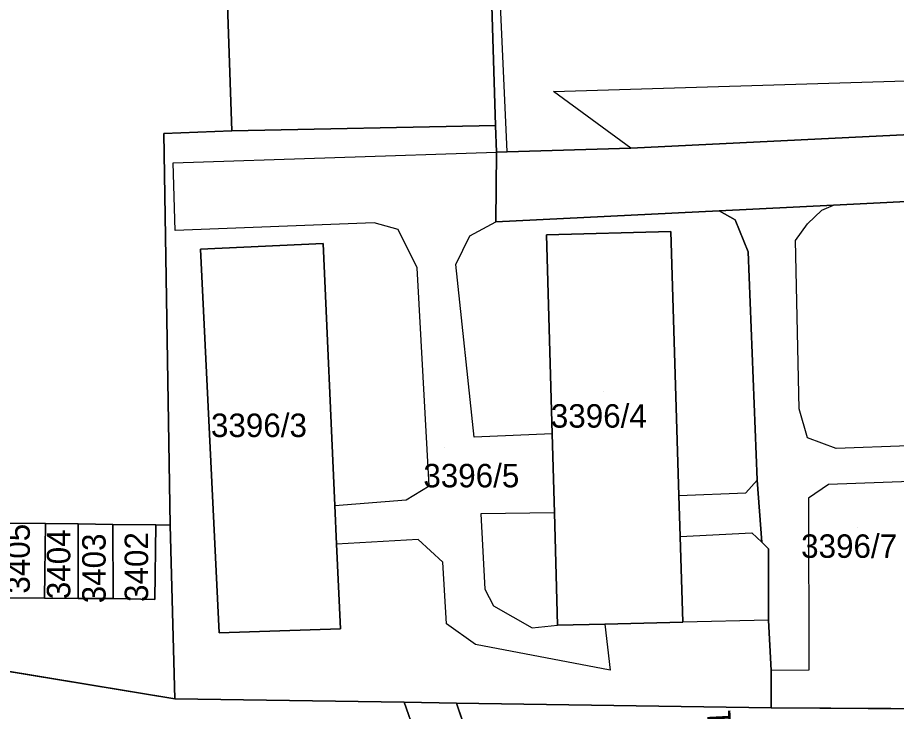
# Model space of a CAD drawing. Extents: x -264070 to -262271, y -1238894 to -1238141.
# Drawn here: x -262723.1 to -262648.2, y -1238480.7 to -1238421.6 of the extents above; entities that cross this region are included whole.
import ezdxf

# ---------------------------------------------------------------- set-up
doc = ezdxf.new("R2010")
doc.units = 0
for name, color, linetype in [('body_kn', 7, 'Continuous'), ('kladpar_druhypozemkov', 7, 'Continuous'), ('kladpar_hranice', 7, 'Continuous'), ('kladpar_parcelnecisla', 7, 'Continuous'), ('kladpar_plochy', 7, 'Continuous'), ('zappar_hrandruhpozemk', 7, 'Continuous')]:
    doc.layers.add(name, color=color, linetype=linetype)

msp = doc.modelspace()

# ---------------------------------------------------------------- linework, layer by layer
at = {"layer": 'body_kn'}
for p, q in [((-262677.41, -1238427.88), (-262677.41, -1238427.88)), ((-262682.33, -1238430.79), (-262682.33, -1238430.79)), ((-262682.33, -1238430.79), (-262682.33, -1238430.79)), ((-262710.6, -1238431.46), (-262710.6, -1238431.46)), ((-262704.82, -1238431.24), (-262704.82, -1238431.24)), ((-262682.26, -1238433.07), (-262682.26, -1238433.07)), ((-262681.34, -1238433.03), (-262681.34, -1238433.03)), ((-262681.34, -1238433.03), (-262681.34, -1238433.03)), ((-262670.81, -1238432.73), (-262670.81, -1238432.73)), ((-262670.81, -1238432.73), (-262670.81, -1238432.73)), ((-262709.82, -1238433.98), (-262709.82, -1238433.98)), ((-262653.53, -1238437.57), (-262653.53, -1238437.57)), ((-262653.53, -1238437.57), (-262653.53, -1238437.57)), ((-262663.29, -1238438.06), (-262663.29, -1238438.06)), ((-262654.54, -1238438.01), (-262654.54, -1238438.01)), ((-262692.67, -1238439.1), (-262692.67, -1238439.1)), ((-262682.32, -1238439.01), (-262682.32, -1238439.01)), ((-262661.93, -1238438.83), (-262661.93, -1238438.83)), ((-262709.63, -1238439.73), (-262709.63, -1238439.73)), ((-262690.62, -1238439.65), (-262690.62, -1238439.65)), ((-262667.41, -1238439.84), (-262667.41, -1238439.84)), ((-262667.41, -1238439.84), (-262667.41, -1238439.84)), ((-262655.76, -1238439.16), (-262655.76, -1238439.16)), ((-262684.53, -1238440.19), (-262684.53, -1238440.19)), ((-262678, -1238440.1), (-262678, -1238440.1)), ((-262656.79, -1238440.59), (-262656.79, -1238440.59)), ((-262707.47, -1238441.34), (-262707.47, -1238441.34)), ((-262697.02, -1238440.86), (-262697.02, -1238440.86)), ((-262697.02, -1238440.86), (-262697.02, -1238440.86)), ((-262660.8, -1238441.56), (-262660.8, -1238441.56)), ((-262685.72, -1238442.65), (-262685.72, -1238442.65)), ((-262689.02, -1238442.92), (-262689.02, -1238442.92)), ((-262656.46, -1238454.95), (-262656.46, -1238454.95)), ((-262684.17, -1238457.37), (-262684.17, -1238457.37)), ((-262677.51, -1238457.08), (-262677.51, -1238457.08)), ((-262677.51, -1238457.08), (-262677.51, -1238457.08)), ((-262655.76, -1238457.42), (-262655.76, -1238457.42)), ((-262653.31, -1238458.32), (-262653.31, -1238458.32)), ((-262687.98, -1238461.52), (-262687.98, -1238461.52)), ((-262660.03, -1238461.01), (-262660.03, -1238461.01)), ((-262660.03, -1238461.03), (-262660.03, -1238461.03)), ((-262653.97, -1238461.41), (-262653.97, -1238461.41)), ((-262661, -1238462.1), (-262661, -1238462.1)), ((-262689.96, -1238462.71), (-262689.96, -1238462.71)), ((-262666.71, -1238462.33), (-262666.71, -1238462.33)), ((-262666.71, -1238462.33), (-262666.71, -1238462.33)), ((-262655.66, -1238462.56), (-262655.66, -1238462.56)), ((-262696.02, -1238463.2), (-262696.02, -1238463.2)), ((-262696.02, -1238463.2), (-262696.02, -1238463.2)), ((-262677.32, -1238463.8), (-262677.32, -1238463.8)), ((-262677.32, -1238463.8), (-262677.32, -1238463.8)), ((-262683.59, -1238463.89), (-262683.59, -1238463.89)), ((-262720.69, -1238464.72), (-262720.69, -1238464.72)), ((-262720.69, -1238464.72), (-262720.69, -1238464.72)), ((-262717.89, -1238464.76), (-262717.89, -1238464.76)), ((-262717.89, -1238464.76), (-262717.89, -1238464.76)), ((-262714.94, -1238464.8), (-262714.94, -1238464.8)), ((-262714.94, -1238464.8), (-262714.94, -1238464.8)), ((-262711.29, -1238464.84), (-262711.29, -1238464.84)), ((-262711.29, -1238464.84), (-262711.29, -1238464.84)), ((-262710.05, -1238464.86), (-262710.05, -1238464.86)), ((-262666.6, -1238465.83), (-262666.6, -1238465.83)), ((-262666.6, -1238465.83), (-262666.6, -1238465.83)), ((-262660.5, -1238465.52), (-262660.5, -1238465.52)), ((-262695.88, -1238466.48), (-262695.88, -1238466.48)), ((-262688.93, -1238466.08), (-262688.93, -1238466.08)), ((-262659.65, -1238466.31), (-262659.65, -1238466.31)), ((-262659.08, -1238466.87), (-262659.08, -1238466.87)), ((-262686.84, -1238468.01), (-262686.84, -1238468.01)), ((-262683.25, -1238470.32), (-262683.25, -1238470.32)), ((-262720.77, -1238471.08), (-262720.77, -1238471.08)), ((-262717.91, -1238471.13), (-262717.91, -1238471.13)), ((-262714.92, -1238471.13), (-262714.92, -1238471.13)), ((-262711.37, -1238471.21), (-262711.37, -1238471.21)), ((-262682.51, -1238471.75), (-262682.51, -1238471.75)), ((-262686.51, -1238473.27), (-262686.51, -1238473.27)), ((-262677.05, -1238473.4), (-262677.05, -1238473.4)), ((-262673.01, -1238473.3), (-262673.01, -1238473.3)), ((-262673.01, -1238473.3), (-262673.01, -1238473.3)), ((-262666.38, -1238473.14), (-262666.38, -1238473.14)), ((-262659.07, -1238472.97), (-262659.07, -1238472.97)), ((-262659.07, -1238472.97), (-262659.07, -1238472.97)), ((-262705.88, -1238474.04), (-262705.88, -1238474.04)), ((-262695.56, -1238473.7), (-262695.56, -1238473.7)), ((-262679.22, -1238473.63), (-262679.22, -1238473.63)), ((-262684.03, -1238475.03), (-262684.03, -1238475.03)), ((-262672.58, -1238477.23), (-262672.58, -1238477.23)), ((-262658.86, -1238477.25), (-262658.86, -1238477.25)), ((-262655.63, -1238477.22), (-262655.63, -1238477.22)), ((-262709.67, -1238479.66), (-262709.67, -1238479.66)), ((-262690.11, -1238479.96), (-262690.11, -1238479.96)), ((-262690.11, -1238479.96), (-262690.11, -1238479.96)), ((-262685.67, -1238480.03), (-262685.67, -1238480.03)), ((-262658.86, -1238480.45), (-262658.86, -1238480.45))]:
    msp.add_line(p, q, dxfattribs=at)
at = {"layer": 'kladpar_druhypozemkov'}
for p, q in [((-262673.13, -1238453.45), (-262673.13, -1238453.45)), ((-262701.43, -1238455.05), (-262701.43, -1238455.05)), ((-262686.68, -1238458.26), (-262686.68, -1238458.26)), ((-262651.5, -1238465.1), (-262651.5, -1238465.1)), ((-262719.97, -1238468.13), (-262719.97, -1238468.13)), ((-262717.07, -1238468.28), (-262717.07, -1238468.28)), ((-262713.8, -1238468.49), (-262713.8, -1238468.49))]:
    msp.add_line(p, q, dxfattribs=at)
at = {"layer": 'kladpar_hranice'}
for p, q in [((-262704.82, -1238431.24), (-262682.33, -1238430.79)), ((-262663.29, -1238438.06), (-262653.53, -1238437.57)), ((-262709.67, -1238479.66), (-262690.11, -1238479.96))]:
    msp.add_line(p, q, dxfattribs=at)
for points in [[(-262727.62, -1238375.13), (-262720.72, -1238374.82), (-262719.4, -1238374.76), (-262719.22, -1238391.06), (-262706.19, -1238390.68), (-262704.82, -1238431.24), (-262710.6, -1238431.46), (-262710.05, -1238464.86), (-262711.29, -1238464.84), (-262714.94, -1238464.8), (-262717.89, -1238464.76), (-262720.69, -1238464.72), (-262723.82, -1238464.68)], [(-262642.76, -1238409.16), (-262642.44, -1238426.82), (-262642.39, -1238429.37), (-262623.26, -1238428.79), (-262623.19, -1238430.38), (-262670.81, -1238432.73), (-262681.34, -1238433.03), (-262682.26, -1238433.07), (-262682.33, -1238430.79), (-262683.59, -1238389.92), (-262657.38, -1238389.22), (-262651.01, -1238389.03), (-262650.49, -1238390.42), (-262643.12, -1238390.23), (-262643.09, -1238393.83), (-262682.26, -1238395.14), (-262681.73, -1238410.21), (-262642.76, -1238409.16)], [(-262683.59, -1238389.92), (-262682.33, -1238430.79), (-262704.82, -1238431.24), (-262706.19, -1238390.68), (-262683.59, -1238389.92)], [(-262528.81, -1238443.27), (-262550.25, -1238441.7), (-262558.38, -1238440.81), (-262565.14, -1238438.89), (-262571.97, -1238436.07), (-262583.91, -1238434.36), (-262593.16, -1238434.55), (-262602.72, -1238435.03), (-262622.62, -1238436.02), (-262634.86, -1238436.64), (-262653.53, -1238437.57), (-262663.29, -1238438.06), (-262682.32, -1238439.01), (-262682.26, -1238433.07), (-262681.34, -1238433.03), (-262670.81, -1238432.73), (-262623.19, -1238430.38), (-262610.89, -1238429.75), (-262587.08, -1238428.65)], [(-262682.33, -1238430.79), (-262682.26, -1238433.07), (-262682.32, -1238439.01), (-262663.29, -1238438.06), (-262661.93, -1238438.83), (-262660.8, -1238441.56), (-262660.03, -1238461.01), (-262660.03, -1238461.03), (-262659.65, -1238466.31), (-262659.08, -1238466.87), (-262659.07, -1238472.97), (-262658.86, -1238477.25), (-262658.86, -1238480.45), (-262685.67, -1238480.03), (-262690.11, -1238479.96), (-262709.67, -1238479.66), (-262710.05, -1238464.86), (-262710.6, -1238431.46), (-262704.82, -1238431.24)], [(-262653.53, -1238437.57), (-262634.86, -1238436.64), (-262632.24, -1238437.35), (-262631.44, -1238437.94), (-262630.97, -1238438.64), (-262630.56, -1238439.54), (-262630.46, -1238440.24), (-262628.6, -1238477.34), (-262628.35, -1238477.3), (-262628.25, -1238480.62), (-262658.86, -1238480.45), (-262658.86, -1238477.25), (-262659.07, -1238472.97), (-262659.08, -1238466.87), (-262659.65, -1238466.31), (-262660.03, -1238461.03), (-262660.03, -1238461.01), (-262660.8, -1238441.56), (-262661.93, -1238438.83), (-262663.29, -1238438.06)], [(-262678, -1238440.1), (-262677.51, -1238457.08), (-262677.32, -1238463.8), (-262677.05, -1238473.4), (-262673.01, -1238473.3), (-262666.38, -1238473.14), (-262666.6, -1238465.83), (-262666.71, -1238462.33), (-262667.41, -1238439.84), (-262678, -1238440.1)], [(-262667.41, -1238439.84), (-262666.71, -1238462.33), (-262666.6, -1238465.83), (-262666.38, -1238473.14), (-262673.01, -1238473.3), (-262677.05, -1238473.4), (-262677.32, -1238463.8), (-262677.51, -1238457.08), (-262678, -1238440.1), (-262667.41, -1238439.84)], [(-262695.56, -1238473.7), (-262695.88, -1238466.48), (-262696.02, -1238463.2), (-262697.02, -1238440.86), (-262707.47, -1238441.34), (-262705.88, -1238474.04), (-262695.56, -1238473.7)], [(-262697.02, -1238440.86), (-262696.02, -1238463.2), (-262695.88, -1238466.48), (-262695.56, -1238473.7), (-262705.88, -1238474.04), (-262707.47, -1238441.34), (-262697.02, -1238440.86)], [(-262723.91, -1238471.05), (-262720.77, -1238471.08), (-262717.91, -1238471.13), (-262714.92, -1238471.13), (-262711.37, -1238471.21), (-262711.29, -1238464.84), (-262710.05, -1238464.86), (-262709.67, -1238479.66), (-262729.53, -1238476.4)], [(-262720.69, -1238464.72), (-262720.77, -1238471.08), (-262723.91, -1238471.05), (-262723.82, -1238464.68), (-262720.69, -1238464.72)], [(-262717.89, -1238464.76), (-262717.91, -1238471.13), (-262720.77, -1238471.08), (-262720.69, -1238464.72), (-262717.89, -1238464.76)], [(-262714.94, -1238464.8), (-262714.92, -1238471.13), (-262717.91, -1238471.13), (-262717.89, -1238464.76), (-262714.94, -1238464.8)], [(-262711.29, -1238464.84), (-262711.37, -1238471.21), (-262714.92, -1238471.13), (-262714.94, -1238464.8), (-262711.29, -1238464.84)], [(-262677.42, -1238504.32), (-262685.67, -1238480.03), (-262658.86, -1238480.45), (-262628.25, -1238480.62), (-262619.15, -1238480.68), (-262602.39, -1238476.75), (-262595.04, -1238471.11)], [(-262729.53, -1238476.4), (-262709.67, -1238479.66)], [(-262677.42, -1238504.32), (-262675.32, -1238509.87), (-262674.44, -1238511.49), (-262673.46, -1238512.89), (-262678.41, -1238514.42), (-262680.86, -1238507.1), (-262681.36, -1238505.58), (-262685.87, -1238492.37), (-262686.4, -1238490.8), (-262687.99, -1238486.14), (-262689.19, -1238482.63), (-262690.11, -1238479.96), (-262685.67, -1238480.03), (-262677.42, -1238504.32)], [(-262690.11, -1238479.96), (-262689.19, -1238482.63)]]:
    msp.add_lwpolyline(points, dxfattribs=at)
at = {"layer": 'kladpar_plochy'}
for p, q in [((-262704.82, -1238431.24), (-262682.33, -1238430.79)), ((-262682.33, -1238430.79), (-262682.26, -1238433.07)), ((-262710.6, -1238431.46), (-262704.82, -1238431.24)), ((-262710.05, -1238464.86), (-262710.6, -1238431.46)), ((-262682.26, -1238433.07), (-262682.32, -1238439.01)), ((-262653.53, -1238437.57), (-262634.86, -1238436.64)), ((-262663.29, -1238438.06), (-262653.53, -1238437.57)), ((-262682.32, -1238439.01), (-262663.29, -1238438.06)), ((-262661.93, -1238438.83), (-262663.29, -1238438.06)), ((-262663.29, -1238438.06), (-262661.93, -1238438.83)), ((-262660.8, -1238441.56), (-262661.93, -1238438.83)), ((-262661.93, -1238438.83), (-262660.8, -1238441.56)), ((-262667.41, -1238439.84), (-262678, -1238440.1)), ((-262666.71, -1238462.33), (-262667.41, -1238439.84)), ((-262678, -1238440.1), (-262677.51, -1238457.08)), ((-262697.02, -1238440.86), (-262707.47, -1238441.34)), ((-262707.47, -1238441.34), (-262705.88, -1238474.04)), ((-262696.02, -1238463.2), (-262697.02, -1238440.86)), ((-262660.03, -1238461.01), (-262660.8, -1238441.56)), ((-262660.8, -1238441.56), (-262660.03, -1238461.01)), ((-262677.51, -1238457.08), (-262677.32, -1238463.8)), ((-262660.03, -1238461.03), (-262660.03, -1238461.01)), ((-262660.03, -1238461.01), (-262660.03, -1238461.03)), ((-262659.65, -1238466.31), (-262660.03, -1238461.03)), ((-262660.03, -1238461.03), (-262659.65, -1238466.31)), ((-262666.6, -1238465.83), (-262666.71, -1238462.33)), ((-262695.88, -1238466.48), (-262696.02, -1238463.2)), ((-262677.32, -1238463.8), (-262677.05, -1238473.4)), ((-262711.37, -1238471.21), (-262711.29, -1238464.84)), ((-262711.29, -1238464.84), (-262710.05, -1238464.86)), ((-262710.05, -1238464.86), (-262709.67, -1238479.66)), ((-262709.67, -1238479.66), (-262710.05, -1238464.86)), ((-262666.38, -1238473.14), (-262666.6, -1238465.83)), ((-262695.56, -1238473.7), (-262695.88, -1238466.48)), ((-262659.08, -1238466.87), (-262659.65, -1238466.31)), ((-262659.65, -1238466.31), (-262659.08, -1238466.87)), ((-262659.07, -1238472.97), (-262659.08, -1238466.87)), ((-262659.08, -1238466.87), (-262659.07, -1238472.97)), ((-262723.91, -1238471.05), (-262720.77, -1238471.08)), ((-262720.77, -1238471.08), (-262717.91, -1238471.13)), ((-262717.91, -1238471.13), (-262714.92, -1238471.13)), ((-262714.92, -1238471.13), (-262711.37, -1238471.21)), ((-262677.05, -1238473.4), (-262673.01, -1238473.3)), ((-262673.01, -1238473.3), (-262666.38, -1238473.14)), ((-262658.86, -1238477.25), (-262659.07, -1238472.97)), ((-262659.07, -1238472.97), (-262658.86, -1238477.25)), ((-262705.88, -1238474.04), (-262695.56, -1238473.7)), ((-262709.67, -1238479.66), (-262729.53, -1238476.4)), ((-262729.53, -1238476.4), (-262709.67, -1238479.66)), ((-262658.86, -1238480.45), (-262658.86, -1238477.25)), ((-262658.86, -1238477.25), (-262658.86, -1238480.45)), ((-262690.11, -1238479.96), (-262709.67, -1238479.66)), ((-262709.67, -1238479.66), (-262690.11, -1238479.96)), ((-262685.67, -1238480.03), (-262690.11, -1238479.96)), ((-262690.11, -1238479.96), (-262689.19, -1238482.63)), ((-262658.86, -1238480.45), (-262685.67, -1238480.03)), ((-262677.42, -1238504.32), (-262685.67, -1238480.03)), ((-262685.67, -1238480.03), (-262658.86, -1238480.45)), ((-262628.25, -1238480.62), (-262658.86, -1238480.45)), ((-262658.86, -1238480.45), (-262628.25, -1238480.62))]:
    msp.add_line(p, q, dxfattribs=at)
for points in [[(-262727.62, -1238375.13), (-262720.72, -1238374.82), (-262719.4, -1238374.76), (-262719.22, -1238391.06), (-262706.19, -1238390.68), (-262704.82, -1238431.24), (-262710.6, -1238431.46), (-262710.05, -1238464.86), (-262711.29, -1238464.84), (-262714.94, -1238464.8), (-262717.89, -1238464.76), (-262720.69, -1238464.72), (-262723.82, -1238464.68)], [(-262634.86, -1238436.64), (-262653.53, -1238437.57), (-262663.29, -1238438.06), (-262682.32, -1238439.01), (-262682.26, -1238433.07), (-262681.34, -1238433.03), (-262670.81, -1238432.73), (-262623.19, -1238430.38)]]:
    msp.add_lwpolyline(points, dxfattribs=at)
for points in [[(-262642.76, -1238409.16), (-262642.44, -1238426.82), (-262642.39, -1238429.37), (-262623.26, -1238428.79), (-262623.19, -1238430.38), (-262670.81, -1238432.73), (-262681.34, -1238433.03), (-262682.26, -1238433.07), (-262682.33, -1238430.79), (-262683.59, -1238389.92), (-262657.38, -1238389.22), (-262651.01, -1238389.03), (-262650.49, -1238390.42), (-262643.12, -1238390.23), (-262643.09, -1238393.83), (-262682.26, -1238395.14), (-262681.73, -1238410.21)], [(-262683.59, -1238389.92), (-262682.33, -1238430.79), (-262704.82, -1238431.24), (-262706.19, -1238390.68)], [(-262667.41, -1238439.84), (-262666.71, -1238462.33), (-262666.6, -1238465.83), (-262666.38, -1238473.14), (-262673.01, -1238473.3), (-262677.05, -1238473.4), (-262677.32, -1238463.8), (-262677.51, -1238457.08), (-262678, -1238440.1)], [(-262697.02, -1238440.86), (-262696.02, -1238463.2), (-262695.88, -1238466.48), (-262695.56, -1238473.7), (-262705.88, -1238474.04), (-262707.47, -1238441.34)], [(-262720.69, -1238464.72), (-262720.77, -1238471.08), (-262723.91, -1238471.05), (-262723.82, -1238464.68)], [(-262717.89, -1238464.76), (-262717.91, -1238471.13), (-262720.77, -1238471.08), (-262720.69, -1238464.72)], [(-262714.94, -1238464.8), (-262714.92, -1238471.13), (-262717.91, -1238471.13), (-262717.89, -1238464.76)], [(-262711.29, -1238464.84), (-262711.37, -1238471.21), (-262714.92, -1238471.13), (-262714.94, -1238464.8)], [(-262677.42, -1238504.32), (-262675.32, -1238509.87), (-262674.44, -1238511.49), (-262673.46, -1238512.89), (-262678.41, -1238514.42), (-262680.86, -1238507.1), (-262681.36, -1238505.58), (-262685.87, -1238492.37), (-262686.4, -1238490.8), (-262687.99, -1238486.14), (-262689.19, -1238482.63), (-262690.11, -1238479.96), (-262685.67, -1238480.03)]]:
    msp.add_lwpolyline(points, close=True, dxfattribs=at)
at = {"layer": 'zappar_hrandruhpozemk'}
for p, q in [((-262681.34, -1238433.03), (-262682.37, -1238410.17)), ((-262677.41, -1238427.88), (-262642.44, -1238426.82)), ((-262670.81, -1238432.73), (-262677.41, -1238427.88)), ((-262709.82, -1238433.98), (-262682.26, -1238433.07)), ((-262684.17, -1238457.37), (-262685.72, -1238442.65)), ((-262687.98, -1238461.52), (-262689.02, -1238442.92)), ((-262677.51, -1238457.08), (-262684.17, -1238457.37)), ((-262647.14, -1238458.09), (-262653.31, -1238458.32)), ((-262646.98, -1238461.15), (-262653.97, -1238461.41)), ((-262666.71, -1238462.33), (-262661, -1238462.1)), ((-262666.6, -1238465.83), (-262660.5, -1238465.52)), ((-262660.5, -1238465.52), (-262659.65, -1238466.31)), ((-262682.51, -1238471.75), (-262679.22, -1238473.63)), ((-262684.03, -1238475.03), (-262686.51, -1238473.27)), ((-262679.22, -1238473.63), (-262677.05, -1238473.4)), ((-262659.07, -1238472.97), (-262666.38, -1238473.14))]:
    msp.add_line(p, q, dxfattribs=at)
for points in [[(-262689.02, -1238442.92), (-262690.62, -1238439.65), (-262692.67, -1238439.1), (-262709.63, -1238439.73), (-262709.82, -1238433.98)], [(-262653.31, -1238458.32), (-262655.76, -1238457.42), (-262656.46, -1238454.95), (-262656.79, -1238440.59), (-262655.76, -1238439.16), (-262654.54, -1238438.01), (-262653.53, -1238437.57)], [(-262685.72, -1238442.65), (-262684.53, -1238440.19), (-262682.32, -1238439.01)], [(-262696.02, -1238463.2), (-262689.96, -1238462.71), (-262687.98, -1238461.52)], [(-262661, -1238462.1), (-262660.03, -1238461.03), (-262660.03, -1238461.01)], [(-262653.97, -1238461.41), (-262655.66, -1238462.56), (-262655.63, -1238477.22), (-262658.86, -1238477.25)], [(-262677.32, -1238463.8), (-262683.59, -1238463.89), (-262683.25, -1238470.32), (-262682.51, -1238471.75)], [(-262686.51, -1238473.27), (-262686.84, -1238468.01), (-262688.93, -1238466.08), (-262695.88, -1238466.48)], [(-262673.01, -1238473.3), (-262672.58, -1238477.23), (-262684.03, -1238475.03)]]:
    msp.add_lwpolyline(points, dxfattribs=at)

# ---------------------------------------------------------------- texts
at = {"layer": 'kladpar_parcelnecisla'}
for s, p in [('3396/4', (-262677.625, -1238456.55)), ('3396/3', (-262706.587, -1238457.35)), ('3396/5', (-262688.49, -1238461.64)), ('3396/7', (-262656.297, -1238467.65))]:
    msp.add_text(s, height=2, dxfattribs=at).set_placement(p)
for s, rotation, p in [('3405', 90, (-262722.02, -1238470.699)), ('3404', 90, (-262718.57, -1238471.174)), ('3403', 90, (-262715.56, -1238471.526)), ('3402', 90, (-262711.94, -1238471.41)), ('3392/1', 93, (-262661.904, -1238488.703))]:
    msp.add_text(s, height=2, rotation=rotation, dxfattribs=at).set_placement(p)

doc.saveas('drawing.dxf')
